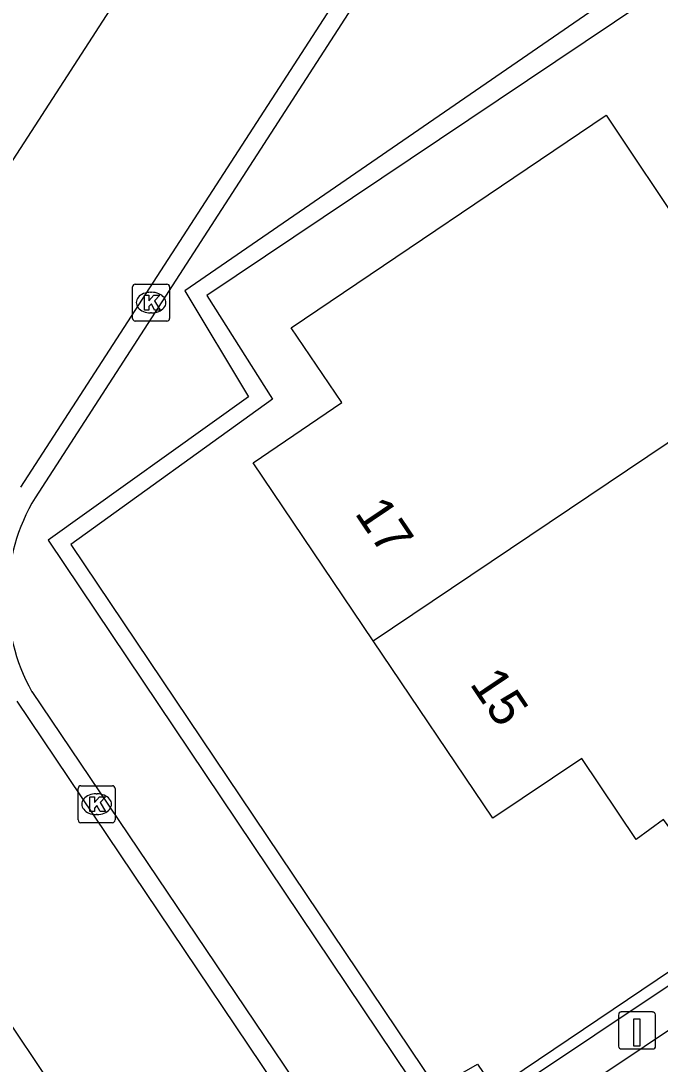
# Model space of a CAD drawing. Extents: x 158797 to 159887, y 384318 to 385255.
# Drawn here: x 158898.46 to 158915.74, y 384626.86 to 384655.06 of the extents above; entities that cross this region are included whole.
import ezdxf

# ---------------------------------------------------------------- set-up
doc = ezdxf.new("R2010")
doc.units = 0
for name, color, linetype in [('IMGEO_Berm_groen', 7, 'Continuous'), ('IMGEO_Groenvoorziening', 7, 'Continuous'), ('IMGEO_Haag', 7, 'Continuous'), ('IMGEO_Hek', 7, 'Continuous'), ('IMGEO_Kolk', 7, 'Continuous'), ('IMGEO_Laadpaal', 7, 'Continuous'), ('IMGEO_Pand', 7, 'Continuous'), ('IMGEO_Pand_nummerreeks', 7, 'Continuous'), ('IMGEO_Parkeervlak_open', 7, 'Continuous'), ('IMGEO_Rijbaan_lokaal_open', 7, 'Continuous')]:
    doc.layers.add(name, color=color, linetype=linetype)

msp = doc.modelspace()

# ---------------------------------------------------------------- linework, layer by layer
at = {"layer": 'IMGEO_Berm_groen'}
msp.add_lwpolyline([(158917.62, 384657.908), (158902.885, 384647.758), (158904.609, 384644.899), (158899.194, 384641.02), (158909.391, 384625.832), (158910.473, 384626.512), (158911.057, 384625.702), (158911.908, 384626.271)], dxfattribs=at)
at = {"layer": 'IMGEO_Groenvoorziening'}
msp.add_lwpolyline([(158917.65, 384657.141), (158903.486, 384647.632), (158905.26, 384644.832), (158899.805, 384640.906), (158909.685, 384626.219), (158910.802, 384626.858), (158911.256, 384626.177), (158922.042, 384633.454), (158922.226, 384633.163)], dxfattribs=at)
at = {"layer": 'IMGEO_Haag'}
msp.add_lwpolyline([(158911.908, 384626.271), (158922.226, 384633.163)], dxfattribs=at)
at = {"layer": 'IMGEO_Hek'}
for points in [[(158918.924, 384652.902), (158920.02, 384653.654), (158917.65, 384657.141), (158903.486, 384647.632), (158905.26, 384644.832)], [(158905.26, 384644.832), (158899.805, 384640.906), (158909.685, 384626.219), (158910.802, 384626.858), (158911.256, 384626.177), (158922.042, 384633.454), (158922.226, 384633.163), (158925.099, 384628.623), (158936.517, 384636.347), (158935.783, 384637.416)]]:
    msp.add_lwpolyline(points, dxfattribs=at)
at = {"layer": 'IMGEO_Kolk'}
for p, q in [((158901.55, 384647.943), (158902.402, 384647.943)), ((158901.475, 384647.017), (158901.475, 384647.869)), ((158901.963, 384647.723), (158901.988, 384647.723)), ((158902.476, 384647.869), (158902.476, 384647.017)), ((158901.986, 384647.163), (158901.961, 384647.163)), ((158902.402, 384646.943), (158901.55, 384646.943)), ((158900.003, 384633.457), (158900.003, 384634.309)), ((158900.078, 384634.383), (158900.93, 384634.383)), ((158900.491, 384634.163), (158900.516, 384634.163)), ((158901.004, 384634.309), (158901.004, 384633.457)), ((158900.514, 384633.603), (158900.489, 384633.603)), ((158900.93, 384633.383), (158900.078, 384633.383))]:
    msp.add_line(p, q, dxfattribs=at)
for points in [[(158901.55, 384647.943), (158902.402, 384647.943)], [(158901.475, 384647.017), (158901.475, 384647.869)], [(158901.796, 384647.643), (158901.919, 384647.643), (158901.919, 384647.492), (158902.049, 384647.643), (158902.213, 384647.643), (158902.067, 384647.492), (158902.22, 384647.243), (158902.068, 384647.243), (158901.983, 384647.407), (158901.919, 384647.34), (158901.919, 384647.243), (158901.796, 384647.243), (158901.796, 384647.643)], [(158902.476, 384647.869), (158902.476, 384647.017)], [(158902.402, 384646.943), (158901.55, 384646.943)], [(158900.003, 384633.457), (158900.003, 384634.309)], [(158900.078, 384634.383), (158900.93, 384634.383)], [(158901.004, 384634.309), (158901.004, 384633.457)], [(158900.324, 384634.083), (158900.447, 384634.083), (158900.447, 384633.932), (158900.577, 384634.083), (158900.741, 384634.083), (158900.595, 384633.932), (158900.748, 384633.683), (158900.596, 384633.683), (158900.511, 384633.847), (158900.447, 384633.78), (158900.447, 384633.683), (158900.324, 384633.683), (158900.324, 384634.083)], [(158900.93, 384633.383), (158900.078, 384633.383)]]:
    msp.add_lwpolyline(points, dxfattribs=at)
for centre, start, end in [((158901.552, 384647.867), 91.552, 178.448), ((158901.552, 384647.867), 91.552, 178.448), ((158902.4, 384647.867), 1.552, 88.448), ((158902.4, 384647.867), 1.552, 88.448), ((158901.552, 384647.019), 181.552, 268.448), ((158901.552, 384647.019), 181.552, 268.448), ((158902.4, 384647.019), 271.552, 358.448), ((158902.4, 384647.019), 271.552, 358.448), ((158900.08, 384634.307), 91.552, 178.448), ((158900.08, 384634.307), 91.552, 178.448), ((158900.928, 384634.307), 1.552, 88.448), ((158900.928, 384634.307), 1.552, 88.448), ((158900.08, 384633.459), 181.552, 268.448), ((158900.08, 384633.459), 181.552, 268.448), ((158900.928, 384633.459), 271.552, 358.448), ((158900.928, 384633.459), 271.552, 358.448)]:
    msp.add_arc(centre, 0.0765, start, end, dxfattribs=at)
for centre, major_axis, ratio, start_param, end_param in [((158901.962, 384647.443), (-0.387, 0.002), 0.722429, 4.712389, 7.853982), ((158901.987, 384647.443), (-0.39, 0.002), 0.717154, 1.570796, 4.712389), ((158900.49, 384633.883), (-0.387, 0.002), 0.722429, 4.712389, 7.853982), ((158900.515, 384633.883), (-0.39, 0.002), 0.717154, 1.570796, 4.712389)]:
    msp.add_ellipse(centre, major_axis=major_axis, ratio=ratio, start_param=start_param, end_param=end_param, dxfattribs=at)
at = {"layer": 'IMGEO_Laadpaal'}
for p, q in [((158914.611, 384628.182), (158914.611, 384627.341)), ((158914.611, 384628.182), (158914.611, 384627.341)), ((158915.527, 384628.266), (158914.686, 384628.266)), ((158915.527, 384628.266), (158914.686, 384628.266)), ((158915.611, 384627.35), (158915.611, 384628.191)), ((158915.611, 384627.35), (158915.611, 384628.191)), ((158914.695, 384627.266), (158915.536, 384627.266)), ((158914.695, 384627.266), (158915.536, 384627.266))]:
    msp.add_line(p, q, dxfattribs=at)
msp.add_lwpolyline([(158915.026, 384628.079), (158915.186, 384628.079), (158915.186, 384627.346), (158915.026, 384627.346), (158915.026, 384628.079)], dxfattribs=at)
for centre, start, end in [((158914.689, 384628.188), 92.4484, 184.2845), ((158914.689, 384628.188), 92.4484, 184.2845), ((158915.533, 384628.188), 2.4484, 94.2845), ((158915.533, 384628.188), 2.4484, 94.2845), ((158914.689, 384627.344), 182.4484, 274.2845), ((158914.689, 384627.344), 182.4484, 274.2845), ((158915.533, 384627.344), 272.4484, 4.2845), ((158915.533, 384627.344), 272.4484, 4.2845)]:
    msp.add_arc(centre, 0.0779, start, end, dxfattribs=at)
at = {"layer": 'IMGEO_Pand'}
for points in [[(158907.976, 384638.304), (158904.737, 384643.112), (158907.129, 384644.742), (158905.762, 384646.758), (158914.28, 384652.511), (158916.47, 384649.231), (158919.852, 384651.521), (158922.28, 384647.917)], [(158907.976, 384638.304), (158922.28, 384647.917)], [(158920.865, 384637.19), (158919.342, 384636.067), (158919.879, 384635.339), (158916.324, 384632.791), (158915.823, 384633.472), (158915.091, 384632.933), (158913.616, 384635.123), (158911.211, 384633.503), (158907.976, 384638.304)]]:
    msp.add_lwpolyline(points, dxfattribs=at)
at = {"layer": 'IMGEO_Parkeervlak_open'}
msp.add_lwpolyline([(158915.86, 384621.72), (158913.074, 384625.843), (158921.951, 384631.78), (158924.728, 384627.665)], dxfattribs=at)
at = {"layer": 'IMGEO_Rijbaan_lokaal_open'}
for points in [[(158898.456, 384642.456), (158912.025, 384663.435)], [(158912.439, 384663.211), (158898.843, 384642.17)], [(158902.408, 384657.762), (158894.078, 384644.875)], [(158898.752, 384636.926), (158909.484, 384621.018)], [(158909.14, 384620.629), (158898.353, 384636.673)], [(158894.038, 384634.089), (158903.158, 384620.5)]]:
    msp.add_lwpolyline(points, dxfattribs=at)
msp.add_arc((158903.322, 384639.469), 5.231, 148.9156, 209.0961, dxfattribs=at)

# ---------------------------------------------------------------- texts
at = {"layer": 'IMGEO_Pand_nummerreeks'}
for s, rotation, p in [('17', 303.968, (158907.461, 384641.752)), ('15', 303.9705, (158910.57, 384637.138))]:
    msp.add_text(s, height=1, rotation=rotation, dxfattribs=at).set_placement(p)

doc.saveas('drawing.dxf')
